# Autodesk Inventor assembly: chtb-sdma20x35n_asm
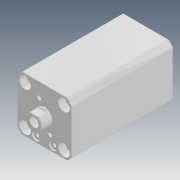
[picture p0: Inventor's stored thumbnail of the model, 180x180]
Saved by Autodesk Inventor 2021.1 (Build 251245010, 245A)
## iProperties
Created: 2018-05
Part Number: chtb-sdma20x35n_asm
Description: STEP AP214
Document SubType Name: Assembly
Designer: user
Title: chtb-sdma20x35n_asm.STEP
Revision Number: ÈÎºÎ
Sending System: SolidWorks 2016
Preprocessor: SwSTEP 2.0
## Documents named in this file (5)
- D:\Vault_2016\Projekty\Clamptek\Hydraulic\CHTB\CHTB-20\Inventor\CHTB-SDMA20x35N\chtb-sdma20x35n_asm.iam
- D:\Vault_2016\Projekty\Clamptek\Hydraulic\CHTB\CHTB-20\Inventor\CHTB-SDMA20x35N\CHTB-SDMA20X35NBT.ipt
- D:\Vault_2016\Projekty\Clamptek\Hydraulic\CHTB\CHTB-20\Inventor\CHTB-SDMA20x35N\CHTB-SDMA20X35NHSG.ipt
- D:\Vault_2016\Projekty\Clamptek\Hydraulic\CHTB\CHTB-20\Inventor\CHTB-SDMA20x35N\QG_3.ipt
- D:\Vault_2016\Projekty\Clamptek\Hydraulic\CHTB\CHTB-20\Inventor\CHTB-SDMA20x35N\socket set screw flat point_iso_ISO 4026 - M5 x 5-N.ipt
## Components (5 placed, 5 different names)
1. CHTB-SDMA20X35NBT_1
2. CHTB-SDMA20X35NHSG_2
3. QG_3_3
4. socket set screw flat point_iso_ISO 4026 - M5 x 5-N_4
5. socket set screw flat point_iso_ISO 4026 - M5 x 5-N_5
